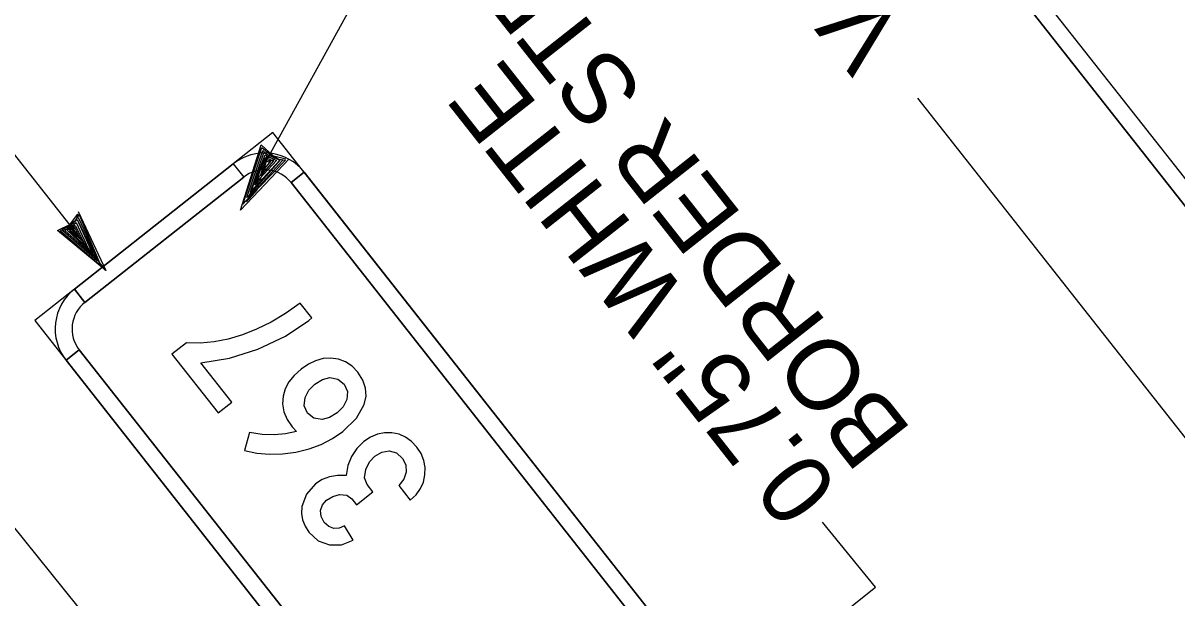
# Model space of a CAD drawing. Extents: x 671946 to 673995, y 1673066 to 1674936.
# Drawn here: x 672609.4 to 672677.9, y 1673572 to 1673606 of the extents above; entities that cross this region are included whole.
import ezdxf

# ---------------------------------------------------------------- set-up
doc = ezdxf.new("R2010")
doc.units = 0
doc.layers.add('C-ANNO-SYMB', color=7, linetype='Continuous')
doc.layers.add('Level 1', color=7, linetype='Continuous')

msp = doc.modelspace()

# ---------------------------------------------------------------- linework, layer by layer
at = {"layer": 'C-ANNO-SYMB'}
for p, q in [((672636.923, 1673647.736), (672688.927, 1673581.77)), ((672639.565, 1673645.999), (672687.855, 1673584.745)), ((672687.07, 1673584.126), (672638.78, 1673645.38)), ((672624.249, 1673599.543), (672610.114, 1673588.399)), ((672624.249, 1673599.543), (672610.114, 1673588.399)), ((672657.681, 1673557.137), (672624.249, 1673599.543)), ((672657.681, 1673557.137), (672624.249, 1673599.543)), ((672612.47, 1673590.257), (672621.893, 1673597.686)), ((672621.893, 1673597.686), (672612.47, 1673590.257)), ((672621.893, 1673597.686), (672622.512, 1673596.901)), ((672621.893, 1673597.686), (672622.512, 1673596.901)), ((672621.893, 1673597.686), (672622.512, 1673596.901)), ((672621.893, 1673597.686), (672622.512, 1673596.901)), ((672625.321, 1673596.568), (672626.106, 1673597.187)), ((672625.321, 1673596.568), (672626.106, 1673597.187)), ((672625.321, 1673596.568), (672626.106, 1673597.187)), ((672626.106, 1673597.187), (672625.321, 1673596.568)), ((672626.106, 1673597.187), (672655.823, 1673559.492)), ((672655.823, 1673559.492), (672626.106, 1673597.187)), ((672622.512, 1673596.901), (672613.089, 1673589.471)), ((672613.089, 1673589.471), (672622.512, 1673596.901)), ((672622.512, 1673596.901), (672622.512, 1673596.901)), ((672622.512, 1673596.901), (672622.512, 1673596.901)), ((672622.512, 1673596.901), (672622.512, 1673596.901)), ((672622.512, 1673596.901), (672622.512, 1673596.901)), ((672655.038, 1673558.873), (672625.321, 1673596.568)), ((672625.321, 1673596.568), (672655.038, 1673558.873)), ((672613.089, 1673589.471), (672612.47, 1673590.257)), ((672613.089, 1673589.471), (672612.47, 1673590.257)), ((672613.089, 1673589.471), (672612.47, 1673590.257)), ((672612.47, 1673590.257), (672613.089, 1673589.471)), ((672610.114, 1673588.399), (672643.545, 1673545.993)), ((672610.114, 1673588.399), (672643.545, 1673545.993)), ((672611.971, 1673586.044), (672612.756, 1673586.663)), ((672611.971, 1673586.044), (672612.756, 1673586.663)), ((672611.971, 1673586.044), (672612.756, 1673586.663)), ((672612.756, 1673586.663), (672611.971, 1673586.044)), ((672612.756, 1673586.663), (672642.473, 1673548.968)), ((672612.756, 1673586.663), (672612.756, 1673586.663)), ((672612.756, 1673586.663), (672612.756, 1673586.663)), ((672612.756, 1673586.663), (672612.756, 1673586.663)), ((672612.756, 1673586.663), (672612.756, 1673586.663)), ((672642.473, 1673548.968), (672612.756, 1673586.663)), ((672641.688, 1673548.349), (672611.971, 1673586.044)), ((672611.971, 1673586.044), (672641.688, 1673548.349))]:
    msp.add_line(p, q, dxfattribs=at)
for points in [[(672621.814, 1673583.565), (672619.978, 1673585.894), (672621.664, 1673586.17), (672623.356, 1673586.706), (672624.985, 1673587.463), (672626.377, 1673588.401), (672626.551, 1673588.548), (672625.86, 1673589.424), (672624.993, 1673588.82), (672624.131, 1673588.306), (672623.28, 1673587.879), (672622.431, 1673587.543), (672621.593, 1673587.293), (672620.76, 1673587.133), (672619.936, 1673587.061), (672619.117, 1673587.08), (672618.254, 1673586.399), (672620.996, 1673582.921)], [(672621.814, 1673583.565), (672619.978, 1673585.894), (672621.664, 1673586.17), (672623.356, 1673586.706), (672624.985, 1673587.463), (672626.377, 1673588.401), (672626.551, 1673588.548), (672625.86, 1673589.424), (672624.993, 1673588.82), (672624.131, 1673588.306), (672623.28, 1673587.879), (672622.431, 1673587.543), (672621.593, 1673587.293), (672620.76, 1673587.133), (672619.936, 1673587.061), (672619.117, 1673587.08), (672618.254, 1673586.399), (672620.996, 1673582.921)], [(672632.396, 1673577.748), (672632.736, 1673578.071), (672632.991, 1673578.431), (672633.169, 1673578.822), (672633.264, 1673579.249), (672633.279, 1673579.683), (672633.203, 1673580.104), (672633.039, 1673580.504), (672632.781, 1673580.892), (672632.467, 1673581.229), (672632.113, 1673581.481), (672631.725, 1673581.651), (672631.297, 1673581.736), (672630.863, 1673581.736), (672630.441, 1673581.649), (672630.036, 1673581.475), (672629.645, 1673581.219), (672629.219, 1673580.811), (672628.9, 1673580.339), (672628.69, 1673579.805), (672628.585, 1673579.215), (672628.079, 1673579.217), (672627.609, 1673579.134), (672627.176, 1673578.965), (672626.778, 1673578.708), (672626.228, 1673578.101), (672625.96, 1673577.37), (672625.94, 1673576.961), (672626.002, 1673576.572), (672626.149, 1673576.199), (672626.379, 1673575.844), (672626.932, 1673575.344), (672627.6, 1673575.096), (672628.313, 1673575.103), (672628.996, 1673575.379), (672628.489, 1673576.235), (672628.184, 1673576.086), (672627.864, 1673576.069), (672627.557, 1673576.182), (672627.29, 1673576.428), (672627.105, 1673576.771), (672627.069, 1673577.132), (672627.183, 1673577.469), (672627.433, 1673577.752), (672627.796, 1673577.969), (672628.196, 1673578.079), (672628.627, 1673578.044), (672628.931, 1673577.826), (672629.209, 1673577.473), (672630.176, 1673578.235), (672629.834, 1673578.669), (672629.674, 1673579.073), (672629.752, 1673579.572), (672629.974, 1673580.01), (672630.293, 1673580.35), (672630.715, 1673580.595), (672631.138, 1673580.664), (672631.57, 1673580.546), (672631.936, 1673580.226), (672632.135, 1673579.838), (672632.149, 1673579.405), (672632.001, 1673578.982), (672631.706, 1673578.624)], [(672632.396, 1673577.748), (672632.736, 1673578.071), (672632.991, 1673578.431), (672633.169, 1673578.822), (672633.264, 1673579.249), (672633.279, 1673579.683), (672633.203, 1673580.104), (672633.039, 1673580.504), (672632.781, 1673580.892), (672632.467, 1673581.229), (672632.113, 1673581.481), (672631.725, 1673581.651), (672631.297, 1673581.736), (672630.863, 1673581.736), (672630.441, 1673581.649), (672630.036, 1673581.475), (672629.645, 1673581.219), (672629.219, 1673580.811), (672628.9, 1673580.339), (672628.69, 1673579.805), (672628.585, 1673579.215), (672628.079, 1673579.217), (672627.609, 1673579.134), (672627.176, 1673578.965), (672626.778, 1673578.708), (672626.228, 1673578.101), (672625.96, 1673577.37), (672625.94, 1673576.961), (672626.002, 1673576.572), (672626.149, 1673576.199), (672626.379, 1673575.844), (672626.932, 1673575.344), (672627.6, 1673575.096), (672628.313, 1673575.103), (672628.996, 1673575.379), (672628.489, 1673576.235), (672628.184, 1673576.086), (672627.864, 1673576.069), (672627.557, 1673576.182), (672627.29, 1673576.428), (672627.105, 1673576.771), (672627.069, 1673577.132), (672627.183, 1673577.469), (672627.433, 1673577.752), (672627.796, 1673577.969), (672628.196, 1673578.079), (672628.627, 1673578.044), (672628.931, 1673577.826), (672629.209, 1673577.473), (672630.176, 1673578.235), (672629.834, 1673578.669), (672629.674, 1673579.073), (672629.752, 1673579.572), (672629.974, 1673580.01), (672630.293, 1673580.35), (672630.715, 1673580.595), (672631.138, 1673580.664), (672631.57, 1673580.546), (672631.936, 1673580.226), (672632.135, 1673579.838), (672632.149, 1673579.405), (672632.001, 1673578.982), (672631.706, 1673578.624)]]:
    msp.add_lwpolyline(points, close=True, dxfattribs=at)
for points in [[(672622.859, 1673581.753), (672622.554, 1673580.695), (672623.289, 1673580.536), (672624.043, 1673580.469), (672624.817, 1673580.489), (672625.611, 1673580.598), (672626.389, 1673580.786), (672627.11, 1673581.055), (672627.78, 1673581.398), (672628.389, 1673581.821), (672629.199, 1673582.607), (672629.658, 1673583.415), (672629.77, 1673583.905), (672629.746, 1673584.387), (672629.583, 1673584.859), (672629.284, 1673585.328), (672628.939, 1673585.692), (672628.553, 1673585.954), (672628.127, 1673586.114), (672627.66, 1673586.171), (672627.219, 1673586.136), (672626.78, 1673586.014), (672626.347, 1673585.806), (672625.915, 1673585.512), (672625.511, 1673585.145), (672625.197, 1673584.757), (672624.979, 1673584.346), (672624.848, 1673583.914), (672624.819, 1673583.448), (672624.897, 1673582.989), (672625.084, 1673582.534), (672625.378, 1673582.089), (672625.638, 1673581.819), (672624.995, 1673581.674), (672624.316, 1673581.613), (672623.604, 1673581.64), (672622.859, 1673581.753)], [(672622.859, 1673581.753), (672622.554, 1673580.695), (672623.289, 1673580.536), (672624.043, 1673580.469), (672624.817, 1673580.489), (672625.611, 1673580.598), (672626.389, 1673580.786), (672627.11, 1673581.055), (672627.78, 1673581.398), (672628.389, 1673581.821), (672629.199, 1673582.607), (672629.658, 1673583.415), (672629.77, 1673583.905), (672629.746, 1673584.387), (672629.583, 1673584.859), (672629.284, 1673585.328), (672628.939, 1673585.692), (672628.553, 1673585.954), (672628.127, 1673586.114), (672627.66, 1673586.171), (672627.219, 1673586.136), (672626.78, 1673586.014), (672626.347, 1673585.806), (672625.915, 1673585.512), (672625.511, 1673585.145), (672625.197, 1673584.757), (672624.979, 1673584.346), (672624.848, 1673583.914), (672624.819, 1673583.448), (672624.897, 1673582.989), (672625.084, 1673582.534), (672625.378, 1673582.089), (672625.638, 1673581.819), (672624.995, 1673581.674), (672624.316, 1673581.613), (672623.604, 1673581.64), (672622.859, 1673581.753)], [(672628.051, 1673582.925), (672627.608, 1673582.653), (672627.159, 1673582.534), (672626.679, 1673582.604), (672626.296, 1673582.908), (672626.098, 1673583.348), (672626.152, 1673583.841), (672626.373, 1673584.262), (672626.734, 1673584.63), (672627.177, 1673584.896), (672627.625, 1673585.011), (672628.096, 1673584.927), (672628.471, 1673584.622), (672628.667, 1673584.194), (672628.622, 1673583.707), (672628.405, 1673583.288), (672628.051, 1673582.925)], [(672628.051, 1673582.925), (672627.608, 1673582.653), (672627.159, 1673582.534), (672626.679, 1673582.604), (672626.296, 1673582.908), (672626.098, 1673583.348), (672626.152, 1673583.841), (672626.373, 1673584.262), (672626.734, 1673584.63), (672627.177, 1673584.896), (672627.625, 1673585.011), (672628.096, 1673584.927), (672628.471, 1673584.622), (672628.667, 1673584.194), (672628.622, 1673583.707), (672628.405, 1673583.288), (672628.051, 1673582.925)]]:
    msp.add_lwpolyline(points, dxfattribs=at)
for centre, radius, start, end in [((672623.751, 1673595.33), 3, 38.2506, 128.25081), ((672623.751, 1673595.33), 3, 38.2506, 128.25081), ((672623.751, 1673595.33), 2, 38.2506, 128.25081), ((672623.751, 1673595.33), 2, 38.2506, 128.25081), ((672614.327, 1673587.901), 3, 128.25054, 218.25075), ((672614.327, 1673587.901), 3, 128.25054, 218.25075), ((672614.327, 1673587.901), 2, 128.25054, 218.25075), ((672614.327, 1673587.901), 2, 128.25054, 218.25075)]:
    msp.add_arc(centre, radius, start, end, dxfattribs=at)
at = {"layer": 'Level 1'}
for p, q in [((672614.326, 1673591.355), (672604.668, 1673603.606)), ((672682.255, 1673576.51), (672662.493, 1673601.577)), ((672622.324, 1673594.937), (672623.54, 1673598.804)), ((672622.452, 1673595.263), (672623.58, 1673598.646)), ((672623.54, 1673598.804), (672624.237, 1673598.186)), ((672623.58, 1673598.646), (672624.148, 1673598.205)), ((672625.215, 1673597.987), (672622.324, 1673594.937)), ((672624.813, 1673597.873), (672622.482, 1673595.311)), ((672624.997, 1673597.899), (672622.61, 1673595.468)), ((672622.701, 1673595.681), (672623.643, 1673598.474)), ((672622.884, 1673595.868), (672623.791, 1673598.221)), ((672624.662, 1673597.898), (672622.884, 1673595.868)), ((672622.908, 1673596.022), (672623.696, 1673598.341)), ((672624.662, 1673597.898), (672622.908, 1673596.022)), ((672623.216, 1673596.537), (672623.791, 1673598.053)), ((672624.457, 1673597.888), (672623.216, 1673596.537)), ((672623.504, 1673596.962), (672623.805, 1673597.91)), ((672624.276, 1673597.864), (672623.504, 1673596.962)), ((672623.846, 1673598.089), (672623.629, 1673597.12)), ((672623.643, 1673598.474), (672623.885, 1673598.264)), ((672623.696, 1673598.341), (672624.662, 1673597.898)), ((672624.148, 1673597.872), (672623.729, 1673597.394)), ((672623.729, 1673597.394), (672623.866, 1673597.843)), ((672623.791, 1673598.221), (672624.457, 1673597.888)), ((672623.791, 1673598.053), (672624.276, 1673597.864)), ((672623.805, 1673597.91), (672624.148, 1673597.872)), ((672624.334, 1673597.961), (672623.846, 1673598.089)), ((672623.866, 1673597.843), (672623.975, 1673597.809)), ((672623.885, 1673598.264), (672624.662, 1673597.898)), ((672623.975, 1673597.809), (672624.334, 1673597.961)), ((672624.148, 1673598.205), (672625.015, 1673597.988)), ((672624.237, 1673598.186), (672624.604, 1673597.966)), ((672624.604, 1673597.966), (672624.997, 1673597.899)), ((672624.768, 1673597.967), (672624.813, 1673597.873)), ((672623.629, 1673597.12), (672623.411, 1673596.918)), ((672623.411, 1673596.918), (672623.181, 1673596.423)), ((672623.181, 1673596.423), (672623.541, 1673596.805)), ((672622.682, 1673595.423), (672623.327, 1673596.168)), ((672623.327, 1673596.168), (672622.701, 1673595.681)), ((672612.187, 1673594.044), (672612.674, 1673594.705)), ((672612.549, 1673594.348), (672612.743, 1673594.658)), ((672612.674, 1673594.705), (672612.606, 1673594.487)), ((672612.606, 1673594.487), (672612.701, 1673594.493)), ((672612.695, 1673594.851), (672614.326, 1673591.355)), ((672612.701, 1673594.493), (672614.064, 1673591.621)), ((672612.743, 1673594.658), (672613.976, 1673591.783)), ((672611.466, 1673593.736), (672612.234, 1673594.113)), ((672614.326, 1673591.355), (672611.466, 1673593.736)), ((672611.615, 1673593.715), (672612.187, 1673594.044)), ((672614.095, 1673591.578), (672611.615, 1673593.715)), ((672611.783, 1673593.709), (672612.046, 1673593.841)), ((672613.827, 1673591.935), (672611.783, 1673593.709)), ((672611.914, 1673593.708), (672612.627, 1673594.374)), ((672613.609, 1673592.23), (672611.914, 1673593.708)), ((672612.046, 1673593.841), (672612.627, 1673594.374)), ((672612.049, 1673593.746), (672612.564, 1673594.196)), ((672613.732, 1673592.156), (672612.049, 1673593.746)), ((672612.459, 1673594.117), (672612.181, 1673593.747)), ((672612.181, 1673593.747), (672612.928, 1673593.225)), ((672612.192, 1673593.688), (672612.522, 1673594.034)), ((672612.234, 1673594.113), (672612.549, 1673594.348)), ((672612.318, 1673593.65), (672612.47, 1673593.928)), ((672612.396, 1673593.678), (672612.463, 1673593.759)), ((672612.463, 1673593.759), (672612.459, 1673594.117)), ((672612.47, 1673593.928), (672612.73, 1673593.405)), ((672612.522, 1673594.034), (672613.018, 1673593.063)), ((672612.564, 1673594.196), (672613.279, 1673592.671)), ((672612.627, 1673594.374), (672613.609, 1673592.23)), ((672612.627, 1673594.374), (672613.732, 1673592.156)), ((672613.279, 1673592.671), (672612.192, 1673593.688)), ((672613.018, 1673593.063), (672612.318, 1673593.65)), ((672612.73, 1673593.405), (672612.396, 1673593.678)), ((672612.928, 1673593.225), (672613.023, 1673592.97)), ((672614.061, 1673569.737), (672603.274, 1673583.099))]:
    msp.add_line(p, q, dxfattribs=at)
for points in [[(672623.563, 1673597.342), (672630.275, 1673609.516), (672627.284, 1673613.309)], [(672650.873, 1673565.326), (672659.985, 1673572.586), (672656.848, 1673576.443)]]:
    msp.add_lwpolyline(points, dxfattribs=at)

# ---------------------------------------------------------------- texts
for s, p in [('VAR.', (672661.941, 1673605.327)), ('BORDER STRIP', (672662.212, 1673581.839)), ('0.75" WHITE ', (672657.918, 1673578.454))]:
    msp.add_text(s, height=4.2, rotation=128.25054, dxfattribs=at).set_placement(p)

doc.saveas('drawing.dxf')
